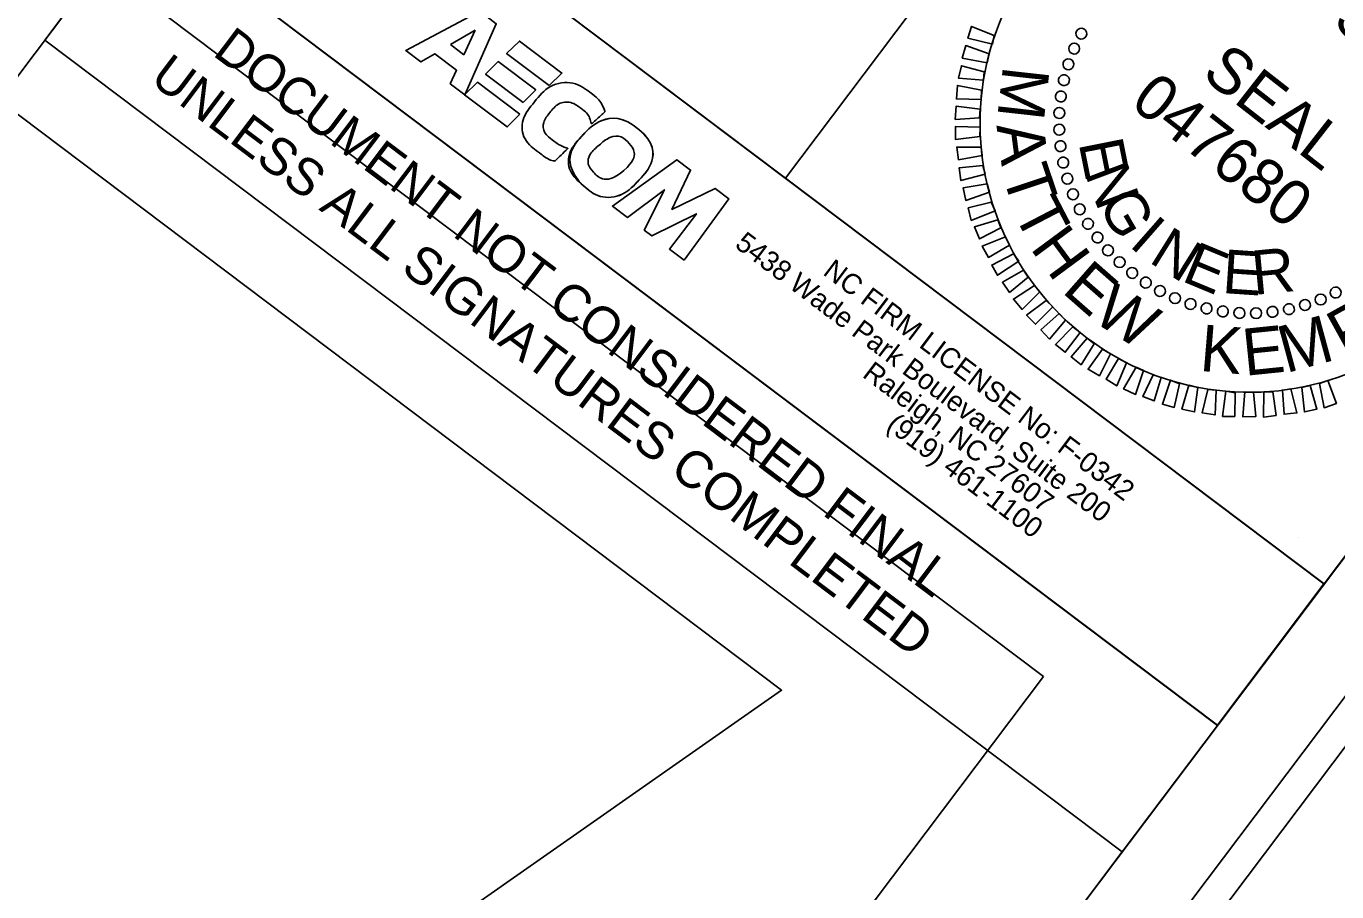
# Model space of a CAD drawing. Extents: x 2296955 to 2298159, y 600182 to 601317.
# Drawn here: x 2297972.1 to 2298088.7, y 600604.2 to 600681.2 of the extents above; entities that cross this region are included whole.
import ezdxf

# ---------------------------------------------------------------- set-up
doc = ezdxf.new("R2010")
doc.units = 0
for name, color, linetype in [('Default', 7, 'Continuous'), ('Exist DTM Drainline Cogo Comment', 7, 'Continuous'), ('Exist DTM Drainline Cogo Elevation', 7, 'Continuous'), ('Exist Property Iron Pin Cogo Number', 7, 'Continuous'), ('Exist Roads Curbs Cogo Comment', 7, 'Continuous'), ('Exist Roads Curbs Cogo Elevation', 7, 'Continuous'), ('Exist Roads Curbs Cogo Number', 7, 'Continuous'), ('Exist Roads Curbs Cogo Point CELL', 7, 'Continuous'), ('Exist Roads EOP Cogo Comment', 7, 'Continuous'), ('Exist Roads EOP Cogo Elevation', 7, 'Continuous'), ('Exist Roads EOP Other Cogo Number', 7, 'Continuous')]:
    doc.layers.add(name, color=color, linetype=linetype)

# ---------------------------------------------------------------- blocks, each defined once
blk = doc.blocks.new('block 3')
at = {"layer": 'Default'}
blk.add_open_spline([(0.12275, 0.09393), (0.12554, 0.09373), (0.12726, 0.09146), (0.12695, 0.08843), (0.12663, 0.08531), (0.12411, 0.08298), (0.12127, 0.08318), (0.11848, 0.08338), (0.11676, 0.08565), (0.11707, 0.08868), (0.11739, 0.0918), (0.11991, 0.09413), (0.12275, 0.09393)], degree=3, dxfattribs=at)
blk = doc.blocks.new('block 2')
at = {"layer": 'Default'}
for p, q in [((0.10234, 0.09375), (0.10197, 0.09133)), ((0.10966, 0.09375), (0.10234, 0.09375)), ((0.10929, 0.09133), (0.10966, 0.09375)), ((0.10197, 0.09133), (0.10929, 0.09133)), ((0.10137, 0.08733), (0.10174, 0.08975)), ((0.10174, 0.08975), (0.10818, 0.08975)), ((0.10818, 0.08975), (0.10782, 0.08733)), ((0.10782, 0.08733), (0.10137, 0.08733)), ((0.10114, 0.08576), (0.10078, 0.08333)), ((0.10846, 0.08576), (0.10114, 0.08576)), ((0.1081, 0.08333), (0.10846, 0.08576)), ((0.10078, 0.08333), (0.1081, 0.08333))]:
    blk.add_line(p, q, dxfattribs=at)
for points in [[(0.10929, 0.09133), (0.10197, 0.09133), (0.10234, 0.09375), (0.10966, 0.09375), (0.10929, 0.09133)], [(0.10782, 0.08733), (0.10137, 0.08733), (0.10174, 0.08975), (0.10818, 0.08975), (0.10782, 0.08733)], [(0.10846, 0.08576), (0.10114, 0.08576), (0.10078, 0.08333), (0.1081, 0.08333), (0.10846, 0.08576)]]:
    blk.add_lwpolyline(points, dxfattribs=at)

msp = doc.modelspace()

# ---------------------------------------------------------------- linework, layer by layer
at = {"layer": 'Exist DTM Drainline Cogo Comment'}
msp.add_lwpolyline([(2298148.7, 600700.2), (2297350.15, 601301.97), (2296969.16, 600796.39), (2297767.7, 600194.63)], close=True, dxfattribs=at)
at = {"layer": 'Exist DTM Drainline Cogo Elevation'}
for points in [[(2298141.78, 600703.5), (2297423.02, 601245.14), (2297043.87, 600742.01), (2297762.63, 600200.36)], [(2298032.37, 600757.74), (2298080.31, 600721.61), (2298039.68, 600667.71), (2297991.74, 600703.83)], [(2298080.31, 600721.61), (2298128.23, 600685.5), (2298087.6, 600631.6), (2298039.68, 600667.71)]]:
    msp.add_lwpolyline(points, close=True, dxfattribs=at)
at = {"layer": 'Exist Property Iron Pin Cogo Number'}
msp.add_lwpolyline([(2297342.87, 601088.91), (2297238.27, 600783.77), (2297197.22, 600664.01), (2297465.89, 600461.56), (2297631.65, 600336.65), (2298039.33, 600622.14), (2298039.33, 600622.14), (2297969.72, 600674.6), (2298027.87, 600751.78), (2297428.93, 601203.11)], close=True, dxfattribs=at)
at = {"layer": 'Exist Roads Curbs Cogo Comment'}
msp.add_lwpolyline([(2297991.74, 600703.83), (2298087.58, 600631.61), (2298078.1, 600619.04), (2297982.26, 600691.26)], close=True, dxfattribs=at)
at = {"layer": 'Exist Roads Curbs Cogo Elevation'}
for p, q in [((2297973.78, 600679.99), (2297982.26, 600691.26)), ((2297982.26, 600691.26), (2298078.12, 600619.02)), ((2298069.63, 600607.76), (2297973.78, 600679.99)), ((2298078.11, 600619.02), (2298069.63, 600607.76))]:
    msp.add_line(p, q, dxfattribs=at)
at = {"layer": 'Exist Roads Curbs Cogo Number'}
msp.add_lwpolyline([(2297423.02, 601245.14), (2297043.89, 600742.01), (2297762.65, 600200.36), (2298069.63, 600607.76), (2297973.78, 600679.99), (2298045.93, 600775.73)], close=True, dxfattribs=at)
at = {"layer": 'Exist Roads Curbs Cogo Point CELL'}
msp.add_lwpolyline([(2298158.96, 600709.34), (2297352.03, 601317.42), (2296954.82, 600790.33), (2297761.75, 600182.24)], close=True, dxfattribs=at)
at = {"layer": 'Exist Roads EOP Cogo Comment'}
msp.add_lwpolyline([(2297425.97, 601224.13), (2297064.9, 600744.96), (2297759.7, 600221.37), (2298062.62, 600623.38), (2297966.76, 600695.61), (2298024.92, 600772.78)], close=True, dxfattribs=at)
msp.add_arc((2298080.95, 600672.61), 23.96, 142.9991, 322.9991, dxfattribs=at)
at = {"layer": 'Exist Roads EOP Cogo Elevation'}
for p, q in [((2298012.49, 600682.55), (2298005.89, 600679.07)), ((2298011.14, 600675.12), (2298013.95, 600681.45)), ((2298009.87, 600679.59), (2298012.07, 600680.87)), ((2298012.08, 600680.86), (2298011.07, 600678.69)), ((2298012.07, 600680.87), (2298012.08, 600680.86)), ((2298005.89, 600679.07), (2298007.25, 600678.05)), ((2298011.07, 600678.69), (2298009.87, 600679.59)), ((2298007.25, 600678.05), (2298008.48, 600678.77)), ((2298008.48, 600678.77), (2298010.42, 600677.31)), ((2298010.42, 600677.31), (2298009.85, 600676.09)), ((2298009.85, 600676.09), (2298011.14, 600675.12)), ((2298030.02, 600669.35), (2298024.28, 600665.22)), ((2298029.57, 600664.92), (2298031.23, 600668.43)), ((2298031.23, 600668.43), (2298030.02, 600669.35)), ((2298025.62, 600664.21), (2298028.91, 600666.68)), ((2298028.91, 600666.68), (2298027.11, 600663.09)), ((2298033.42, 600666.79), (2298029.57, 600664.92)), ((2298034.63, 600665.87), (2298033.42, 600666.79)), ((2298024.28, 600665.22), (2298025.62, 600664.21)), ((2298030.67, 600660.4), (2298034.63, 600665.87)), ((2298027.79, 600662.57), (2298031.75, 600664.54)), ((2298031.75, 600664.54), (2298029.35, 600661.4)), ((2298027.11, 600663.09), (2298027.79, 600662.57)), ((2298029.35, 600661.4), (2298030.67, 600660.4))]:
    msp.add_line(p, q, dxfattribs=at)
for points in [[(2298009.85, 600676.09), (2298011.14, 600675.12), (2298013.95, 600681.45), (2298012.49, 600682.55), (2298005.89, 600679.07), (2298007.25, 600678.05), (2298008.48, 600678.77), (2298010.42, 600677.31), (2298009.85, 600676.09)], [(2298030.67, 600660.4), (2298034.63, 600665.87), (2298033.42, 600666.79), (2298029.57, 600664.92), (2298031.23, 600668.43), (2298030.02, 600669.35), (2298024.28, 600665.22), (2298025.62, 600664.21), (2298028.91, 600666.68), (2298027.11, 600663.09), (2298027.79, 600662.57), (2298031.75, 600664.54), (2298029.35, 600661.4), (2298030.67, 600660.4)]]:
    msp.add_lwpolyline(points, dxfattribs=at)
for points in [[(2298020.33, 600670.36), (2298019.84, 600670.47), (2298019.28, 600670.85), (2298019.02, 600671.05), (2298018.16, 600671.69), (2298018.04, 600672.7), (2298018.72, 600673.54), (2298019.44, 600674.43), (2298020.62, 600674.57), (2298021.56, 600673.86), (2298022, 600673.53), (2298022.28, 600673.08), (2298022.41, 600672.52), (2298022.41, 600672.52), (2298023.64, 600673.62), (2298023.64, 600673.62), (2298023.34, 600674.34), (2298022.99, 600674.81), (2298022.43, 600675.23), (2298020.88, 600676.4), (2298018.62, 600676.07), (2298017.34, 600674.49), (2298016.1, 600672.95), (2298016.29, 600671.07), (2298017.82, 600669.93), (2298018.08, 600669.73), (2298018.67, 600669.32), (2298019.16, 600669.22), (2298019.16, 600669.22), (2298020.33, 600670.36), (2298020.33, 600670.36)], [(2298020.33, 600670.36), (2298019.84, 600670.47), (2298019.28, 600670.85), (2298019.02, 600671.05), (2298018.16, 600671.69), (2298018.04, 600672.7), (2298018.72, 600673.54), (2298019.44, 600674.43), (2298020.62, 600674.57), (2298021.56, 600673.86), (2298022, 600673.53), (2298022.28, 600673.08), (2298022.41, 600672.52), (2298022.41, 600672.52), (2298023.64, 600673.62), (2298023.64, 600673.62), (2298023.34, 600674.34), (2298022.99, 600674.81), (2298022.43, 600675.23), (2298020.88, 600676.4), (2298018.62, 600676.07), (2298017.34, 600674.49), (2298016.1, 600672.95), (2298016.29, 600671.07), (2298017.82, 600669.93), (2298018.08, 600669.73), (2298018.67, 600669.32), (2298019.16, 600669.22), (2298019.16, 600669.22), (2298020.33, 600670.36), (2298020.33, 600670.36)], [(2298021.2, 600667.58), (2298020.34, 600668.74), (2298020.49, 600670.29), (2298021.65, 600671.54), (2298023.04, 600673.03), (2298025.25, 600673.25), (2298026.64, 600672.04)], [(2298026.64, 600672.04), (2298028.01, 600670.85), (2298028.01, 600669), (2298026.67, 600667.55), (2298025.29, 600666.06), (2298023.07, 600665.84), (2298021.68, 600667.06), (2298021.5, 600667.22), (2298021.33, 600667.39), (2298021.2, 600667.58)], [(2298025.29, 600668.39), (2298026.17, 600669.15), (2298026.37, 600670.12), (2298025.79, 600670.78), (2298025.14, 600671.5), (2298024.02, 600671.44), (2298023.09, 600670.64), (2298022.2, 600669.87), (2298022.01, 600668.91), (2298022.59, 600668.25), (2298023.23, 600667.52), (2298024.36, 600667.58), (2298025.29, 600668.39)], [(2298025.29, 600668.39), (2298026.17, 600669.15), (2298026.37, 600670.12), (2298025.79, 600670.78), (2298025.14, 600671.5), (2298024.02, 600671.44), (2298023.09, 600670.64), (2298022.2, 600669.87), (2298022.01, 600668.91), (2298022.59, 600668.25), (2298023.23, 600667.52), (2298024.36, 600667.58), (2298025.29, 600668.39)]]:
    msp.add_open_spline(points, degree=3, dxfattribs=at)
at = {"layer": 'Exist Roads EOP Other Cogo Number'}
for p, q in [((2298066.02, 600680.56), (2298066.02, 600680.56)), ((2298065.34, 600679.21), (2298065.34, 600679.21)), ((2298064.81, 600677.84), (2298064.81, 600677.84)), ((2298064.43, 600676.44), (2298064.43, 600676.44)), ((2298064.18, 600674.98), (2298064.18, 600674.98)), ((2298064.03, 600673.49), (2298064.03, 600673.49)), ((2298063.99, 600672.04), (2298063.99, 600672.04)), ((2298080.95, 600672.61), (2298080.95, 600672.61)), ((2298064.13, 600670.54), (2298064.13, 600670.54)), ((2298064.35, 600669.1), (2298064.35, 600669.1)), ((2298064.75, 600667.66), (2298064.75, 600667.66)), ((2298065.21, 600666.25), (2298065.21, 600666.25)), ((2298065.86, 600664.92), (2298065.86, 600664.92)), ((2298066.57, 600663.63), (2298066.57, 600663.63)), ((2298067.42, 600662.4), (2298067.42, 600662.4)), ((2298068.37, 600661.3), (2298068.37, 600661.3)), ((2298069.38, 600660.24), (2298069.38, 600660.24)), ((2298070.51, 600659.26), (2298070.51, 600659.26)), ((2298071.71, 600658.4), (2298071.71, 600658.4)), ((2298072.99, 600657.68), (2298072.99, 600657.68)), ((2298074.34, 600657.01), (2298074.34, 600657.01)), ((2298087.3, 600656.88), (2298087.3, 600656.88)), ((2298088.63, 600657.52), (2298088.63, 600657.52)), ((2298075.72, 600656.48), (2298075.72, 600656.48)), ((2298077.12, 600656.1), (2298077.12, 600656.1)), ((2298078.58, 600655.84), (2298078.58, 600655.84)), ((2298080.07, 600655.69), (2298080.07, 600655.69)), ((2298081.52, 600655.65), (2298081.52, 600655.65)), ((2298083.02, 600655.79), (2298083.02, 600655.79)), ((2298084.46, 600656.02), (2298084.46, 600656.02)), ((2298085.9, 600656.41), (2298085.9, 600656.41)), ((2298085.36, 600635.73), (2298085.36, 600635.73))]:
    msp.add_line(p, q, dxfattribs=at)
for points in [[(2298058.08, 600679.62), (2298055.91, 600680.15), (2298056.24, 600681.21), (2298058.24, 600680.39)], [(2298057.61, 600677.98), (2298055.41, 600678.37), (2298055.71, 600679.5), (2298057.79, 600678.78)], [(2298057.28, 600676.42), (2298055.06, 600676.61), (2298055.33, 600677.71), (2298057.34, 600677.17)], [(2298057.08, 600674.7), (2298054.88, 600674.76), (2298054.98, 600675.95), (2298057.11, 600675.53)], [(2298056.95, 600673.07), (2298054.78, 600672.93), (2298054.85, 600674.1), (2298057.01, 600673.83)], [(2298056.97, 600671.41), (2298054.81, 600671.13), (2298054.8, 600672.29), (2298057, 600672.23)], [(2298057.18, 600669.73), (2298055.07, 600669.34), (2298054.91, 600670.47), (2298057.1, 600670.47)], [(2298057.44, 600668.05), (2298055.28, 600667.49), (2298055.12, 600668.62), (2298057.23, 600668.84)], [(2298057.83, 600666.45), (2298055.72, 600665.72), (2298055.47, 600666.84), (2298057.61, 600667.21)], [(2298058.33, 600664.81), (2298056.21, 600663.95), (2298055.93, 600665.05), (2298057.98, 600665.58)], [(2298058.83, 600663.29), (2298056.95, 600662.3), (2298056.48, 600663.37), (2298058.56, 600664)], [(2298059.6, 600661.73), (2298057.73, 600660.65), (2298057.18, 600661.66), (2298059.24, 600662.48)], [(2298060.43, 600660.31), (2298058.53, 600659.07), (2298058.02, 600659.97), (2298059.95, 600660.96)], [(2298061.28, 600658.91), (2298059.62, 600657.54), (2298058.98, 600658.44), (2298060.86, 600659.52)], [(2298062.31, 600657.58), (2298060.72, 600656.03), (2298059.96, 600656.94), (2298061.84, 600658.14)], [(2298063.46, 600656.25), (2298061.92, 600654.71), (2298061.13, 600655.51), (2298062.87, 600656.82)], [(2298064.59, 600655.06), (2298063.16, 600653.39), (2298062.4, 600654.22), (2298064.03, 600655.65)], [(2298065.88, 600653.96), (2298064.56, 600652.21), (2298063.69, 600652.91), (2298065.25, 600654.48)], [(2298067.15, 600652.96), (2298065.97, 600651.11), (2298065.1, 600651.8), (2298066.52, 600653.47)], [(2298068.6, 600652.08), (2298067.6, 600650.13), (2298066.6, 600650.71), (2298067.89, 600652.49)], [(2298070.02, 600651.27), (2298069.15, 600649.22), (2298068.2, 600649.81), (2298069.31, 600651.67)], [(2298071.53, 600650.59), (2298070.82, 600648.46), (2298069.76, 600648.96), (2298070.87, 600650.88)], [(2298073.09, 600649.96), (2298072.49, 600647.88), (2298071.47, 600648.27), (2298072.38, 600650.2)], [(2298074.74, 600649.4), (2298074.26, 600647.31), (2298073.21, 600647.59), (2298073.94, 600649.74)], [(2298076.35, 600649.07), (2298076.07, 600646.91), (2298074.95, 600647.16), (2298075.57, 600649.28)], [(2298078, 600648.84), (2298077.9, 600646.64), (2298076.74, 600646.84), (2298077.24, 600648.91)], [(2298079.69, 600648.62), (2298079.65, 600646.5), (2298078.56, 600646.51), (2298078.85, 600648.75)], [(2298081.32, 600648.66), (2298081.51, 600646.49), (2298080.35, 600646.48), (2298080.55, 600648.7)], [(2298083.03, 600648.68), (2298083.32, 600646.6), (2298082.19, 600646.45), (2298082.23, 600648.69)], [(2298084.63, 600648.96), (2298085.17, 600646.82), (2298084.03, 600646.7), (2298083.88, 600648.85)], [(2298086.35, 600649.27), (2298086.96, 600647.16), (2298085.84, 600646.91), (2298085.6, 600649.07)], [(2298087.93, 600649.69), (2298088.69, 600647.67), (2298087.59, 600647.28), (2298087.19, 600649.44)]]:
    msp.add_lwpolyline(points, close=True, dxfattribs=at)
for centre, major_axis in [((2298066, 600680.56), (-0.429, 0.228)), ((2298065.36, 600679.23), (-0.447, 0.19)), ((2298064.85, 600677.84), (-0.462, 0.15)), ((2298064.45, 600676.42), (-0.474, 0.109)), ((2298064.18, 600674.97), (-0.481, 0.068)), ((2298064.04, 600673.5), (-0.485, 0.025)), ((2298064.03, 600672.02), (-0.486, -0.017)), ((2298064.14, 600670.55), (-0.482, -0.059)), ((2298064.39, 600669.09), (-0.475, -0.101)), ((2298064.76, 600667.66), (-0.465, -0.142)), ((2298065.25, 600666.27), (-0.451, -0.182)), ((2298065.86, 600664.93), (-0.433, -0.221)), ((2298066.59, 600663.64), (-0.412, -0.258)), ((2298067.43, 600662.42), (-0.388, -0.292)), ((2298068.37, 600661.28), (-0.361, -0.325)), ((2298069.4, 600660.23), (-0.331, -0.355)), ((2298070.52, 600659.27), (-0.299, -0.383)), ((2298071.73, 600658.41), (-0.265, -0.408)), ((2298073, 600657.66), (-0.228, -0.429)), ((2298088.63, 600657.53), (0.221, -0.433)), ((2298074.33, 600657.03), (-0.19, -0.447)), ((2298075.71, 600656.51), (-0.15, -0.462)), ((2298085.9, 600656.42), (0.142, -0.465)), ((2298087.29, 600656.91), (0.182, -0.451)), ((2298077.14, 600656.12), (-0.109, -0.474)), ((2298078.59, 600655.85), (-0.068, -0.481)), ((2298080.06, 600655.71), (-0.025, -0.485)), ((2298081.54, 600655.69), (0.017, -0.486)), ((2298083.01, 600655.81), (0.059, -0.482)), ((2298084.47, 600656.05), (0.101, -0.475))]:
    msp.add_ellipse(centre, major_axis=major_axis, ratio=0.999708, dxfattribs=at)

# ---------------------------------------------------------------- block references
at = {"layer": 'Exist Roads EOP Cogo Elevation', "xscale": 648.0018668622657, "yscale": 648.0018668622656, "rotation": -37.00085886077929}
for name in ['block 2', 'block 3']:
    msp.add_blockref(name, (2297926.48, 600671.3), dxfattribs=at)

# ---------------------------------------------------------------- texts
at = {"layer": 'Exist Roads Curbs Cogo Elevation'}
for s, p in [('DOCUMENT NOT CONSIDERED FINAL', (2297988.63, 600678.69)), ('UNLESS ALL SIGNATURES COMPLETED', (2297983.02, 600676.3))]:
    msp.add_text(s, height=3.3, rotation=322.9991, dxfattribs=at).set_placement(p)
at = {"layer": 'Exist Roads EOP Cogo Elevation'}
for s, p in [('5438 Wade Park Boulevard, Suite 200', (2298035.08, 600661.62)), ('NC FIRM LICENSE No: F-0342', (2298042.92, 600659.18)), ('Raleigh, NC 27607', (2298046.43, 600650.08)), ('(919) 461-1100', (2298048.55, 600645.48))]:
    msp.add_text(s, height=1.8, rotation=322.9991, dxfattribs=at).set_placement(p)
at = {"layer": 'Exist Roads EOP Other Cogo Number'}
for s, height, rotation, p in [('S', 3.81, 320.8995, (2298088.24, 600681.4)), ('SEAL', 4.049, 321.9991, (2298076.58, 600676.75)), ('M', 4.16, 263.5937, (2298059.04, 600677.78)), ('047680', 4.05, 321.9991, (2298070.22, 600674.18)), ('A', 4.18, 277.4086, (2298058.44, 600672.4)), ('E', 3.93, 281.276, (2298065.75, 600670.84)), ('T', 4.16, 288.4857, (2298058.9, 600668.08)), ('N', 3.9, 290.6331, (2298066.27, 600668.16)), ('T', 4.12, 297.4856, (2298059.88, 600664.69)), ('G', 3.86, 299.9894, (2298067.4, 600665.41)), ('I', 3.81, 318.7003, (2298070.16, 600661.72)), ('H', 4.08, 306.4856, (2298061.38, 600661.49)), ('N', 3.81, 328.0555, (2298071.91, 600660.28)), ('E', 3.83, 337.4109, (2298074.82, 600658.59)), ('E', 3.9, 356.1232, (2298078.47, 600657.49)), ('R', 3.93, 5.4805, (2298081.34, 600657.31)), ('E', 4.05, 318.727, (2298064.18, 600657.6)), ('W', 4.05, 328.0417, (2298066.83, 600655.08)), ('P', 4.13, 28.9814, (2298089.42, 600651.76)), ('K', 4.15, 355.3412, (2298076.45, 600650.56)), ('E', 4.18, 5.8517, (2298080.54, 600650.11)), ('M', 4.18, 15.1664, (2298084.19, 600650.34))]:
    msp.add_text(s, height=height, rotation=rotation, dxfattribs=at).set_placement(p)

doc.saveas('drawing.dxf')
